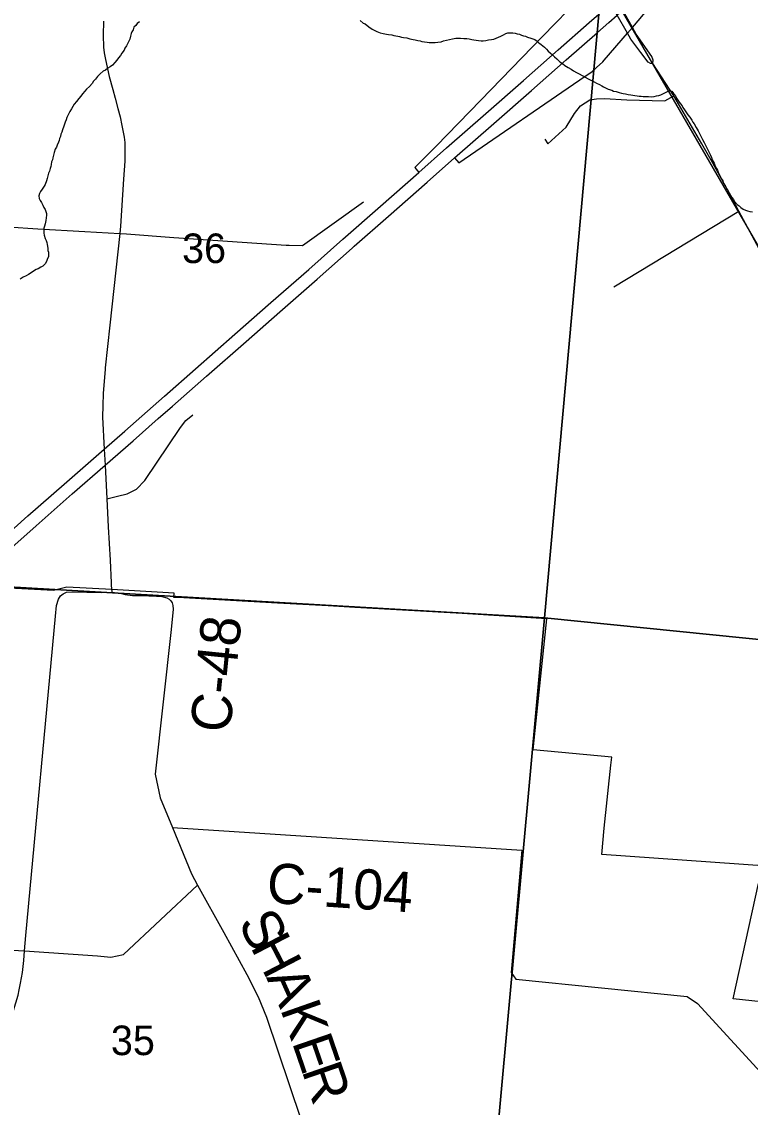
# Model space of a CAD drawing. Extents: x -7.3 to 34, y 0 to 22.
# Drawn here: x 5.697 to 6.729, y 15.258 to 16.795 of the extents above; entities that cross this region are included whole.
import ezdxf

# ---------------------------------------------------------------- set-up
doc = ezdxf.new("R2010")
doc.units = 0
for name, color, linetype in [('GM_X_City_Street', 7, 'Continuous'), ('GM_X_Corporation', 7, 'Continuous'), ('GM_X_County_Road', 7, 'Continuous'), ('GM_X_County_Road_Text', 7, 'Continuous'), ('GM_X_Interchange_Ramps', 7, 'Continuous'), ('GM_X_Interstate_Route', 7, 'Continuous'), ('GM_X_Minor_River', 7, 'Continuous'), ('GM_X_Rail_Line', 7, 'Continuous'), ('GM_X_Section_Text', 7, 'Continuous'), ('GM_X_State_Route', 7, 'Continuous'), ('GM_X_Township_Road', 7, 'Continuous')]:
    doc.layers.add(name, color=color, linetype=linetype)

msp = doc.modelspace()

# ---------------------------------------------------------------- linework, layer by layer
at = {"layer": 'GM_X_City_Street'}
for p, q in [((6.0944, 16.4782), (6.1808, 16.5402)), ((6.5355, 16.4199), (6.7126, 16.5267))]:
    msp.add_line(p, q, dxfattribs=at)
for points in [[(6.438, 16.629), (6.4421, 16.6224), (6.4681, 16.6457), (6.4797, 16.6651), (6.4884, 16.676), (6.5014, 16.6844), (6.5111, 16.6862), (6.5222, 16.6866), (6.5538, 16.6848), (6.6077, 16.6833), (6.6205, 16.6905)], [(5.817, 16.1194), (5.8323, 16.1231), (5.8461, 16.1267), (5.8591, 16.1332), (5.8709, 16.1456), (5.9218, 16.2206), (5.9292, 16.2303), (5.939, 16.2382)]]:
    msp.add_lwpolyline(points, dxfattribs=at)
at = {"layer": 'GM_X_Corporation'}
for points in [[(6.5281, 16.9583), (6.4371, 15.9508), (5.3843, 16.0117), (5.4793, 17.0267)], [(7.5781, 16.8709), (7.4799, 15.8457), (6.4371, 15.9508), (6.5281, 16.9583)], [(5.3843, 16.0117), (6.4371, 15.9508), (6.3438, 14.9266), (5.2968, 14.9953)], [(6.4371, 15.9508), (7.4799, 15.8457), (7.3939, 14.8252), (6.3438, 14.9266)]]:
    msp.add_lwpolyline(points, close=True, dxfattribs=at)
for points in [[(6.7526, 15.5989), (6.5186, 15.6157), (6.522, 15.653), (6.5314, 15.7421), (6.5326, 15.7533), (6.4213, 15.7638), (6.4256, 15.8049), (6.4405, 15.9496), (6.3205, 15.9572), (6.1686, 15.9656), (6.1308, 15.9677), (6.059, 15.9717), (5.918, 15.9795), (5.9123, 15.9798), (5.9126, 15.9859), (5.8241, 15.9908), (5.7607, 15.9943), (5.7415, 15.9894), (5.6604, 15.9938)], [(6.7577, 15.4057), (6.7044, 15.4109), (6.7404, 15.5743)]]:
    msp.add_lwpolyline(points, dxfattribs=at)
at = {"layer": 'GM_X_County_Road'}
for points in [[(5.8123, 16.7959), (5.8119, 16.776), (5.8127, 16.7593), (5.8135, 16.7514), (5.8152, 16.7418), (5.8205, 16.7178), (5.8255, 16.6994), (5.8289, 16.6868), (5.8327, 16.6725), (5.836, 16.6604), (5.8386, 16.6483), (5.8405, 16.6388), (5.8416, 16.6318), (5.8425, 16.624), (5.8429, 16.6151), (5.8428, 16.6085), (5.8425, 16.5979), (5.8408, 16.5721), (5.8366, 16.5057), (5.8357, 16.4953), (5.8213, 16.3654), (5.8147, 16.3051), (5.8146, 16.3031)], [(5.8146, 16.3031), (5.812, 16.2688), (5.8115, 16.2516)], [(5.8115, 16.2516), (5.8111, 16.2353), (5.8135, 16.1898), (5.8147, 16.1671), (5.817, 16.1194), (5.8189, 16.0796), (5.8217, 16.0324), (5.8233, 16.0003), (5.8235, 15.9973)], [(5.8235, 15.9973), (5.8242, 15.987), (5.8359, 15.9856), (5.843, 15.9839), (5.8535, 15.9827), (5.8654, 15.9823), (5.8876, 15.9815), (5.8951, 15.9811), (5.9021, 15.9793), (5.9054, 15.9775), (5.908, 15.9751), (5.9097, 15.972), (5.9108, 15.9682), (5.9111, 15.9632), (5.9082, 15.9345), (5.8859, 15.7294), (5.8926, 15.6958), (5.9101, 15.654)], [(5.7005, 15.479), (5.7025, 15.501), (5.7446, 15.953), (5.746, 15.9682), (5.7485, 15.9775), (5.7517, 15.9821), (5.7551, 15.9849), (5.76, 15.987), (5.7672, 15.9879), (5.8101, 15.9867), (5.8242, 15.987)], [(5.9101, 15.654), (5.9371, 15.588), (5.9458, 15.5723)], [(5.9101, 15.654), (6.405, 15.6216), (6.39, 15.4485), (6.3969, 15.4388), (6.6396, 15.4146), (6.6541, 15.4047), (7.0106, 15.016), (7.0281, 15.003), (7.4002, 14.9537)], [(5.2631, 15.5069), (5.2998, 15.5038), (5.3423, 15.5008), (5.4051, 15.4965), (5.4762, 15.4913), (5.5226, 15.4888), (5.5852, 15.4858), (5.6578, 15.4813), (5.7005, 15.479), (5.8041, 15.4719), (5.823, 15.4702), (5.841, 15.4739), (5.9458, 15.5723)], [(5.9458, 15.5723), (5.983, 15.5051), (6.0156, 15.4458), (6.0314, 15.4138), (6.0435, 15.385), (6.1085, 15.1916), (6.1202, 15.1639), (6.1228, 15.1187), (6.1105, 14.9604), (6.1114, 14.9539), (6.1126, 14.9497), (6.1149, 14.9453), (6.1189, 14.9421), (6.124, 14.9396), (6.1297, 14.9384), (6.135, 14.9379), (6.1434, 14.9376), (6.3268, 14.9272), (6.3325, 14.9245), (6.3377, 14.9197), (6.3407, 14.9122), (6.3395, 14.9005), (6.265, 14.1)], [(5.219, 14.1), (5.2383, 14.3304), (5.2709, 14.7021), (5.2768, 14.7107), (5.3257, 14.7637), (5.4619, 14.9128), (5.492, 14.945), (5.517, 14.9838), (5.5831, 15.0835), (5.6007, 15.1153), (5.611, 15.1424), (5.6526, 15.2909), (5.6914, 15.4165), (5.6931, 15.4241), (5.695, 15.4332), (5.6976, 15.4484), (5.6994, 15.4652), (5.7005, 15.479)]]:
    msp.add_lwpolyline(points, dxfattribs=at)
at = {"layer": 'GM_X_Interchange_Ramps'}
for p, q in [((6.522, 16.7408), (6.5551, 16.7789)), ((6.5551, 16.7789), (6.5621, 16.7871))]:
    msp.add_line(p, q, dxfattribs=at)
for points in [[(6.5621, 16.7871), (6.5649, 16.7906), (6.5956, 16.8273), (6.6184, 16.8544), (6.6365, 16.8741), (6.6473, 16.8856), (6.6419, 16.8935)], [(6.5195, 16.8633), (6.5117, 16.8544), (6.4889, 16.8307), (6.4346, 16.7745), (6.3469, 16.6841), (6.284, 16.6192), (6.2535, 16.589), (6.2594, 16.5819)], [(6.3099, 16.6023), (6.316, 16.5953), (6.495, 16.7181), (6.5042, 16.7241), (6.5112, 16.7302), (6.52, 16.7385), (6.522, 16.7408)]]:
    msp.add_lwpolyline(points, dxfattribs=at)
at = {"layer": 'GM_X_Interstate_Route'}
for points in [[(6.5285, 16.7942), (6.5403, 16.8047), (6.5484, 16.8118), (6.5982, 16.8552), (6.6419, 16.8935), (6.7013, 16.9459), (6.8071, 17.039), (6.8463, 17.0736), (6.8936, 17.1174), (6.9089, 17.1322)], [(6.2594, 16.5819), (6.2984, 16.6165), (6.354, 16.6652), (6.4075, 16.712), (6.4567, 16.7553), (6.5008, 16.794), (6.5313, 16.8207)], [(6.1676, 16.4771), (6.2165, 16.5199), (6.271, 16.5681), (6.3099, 16.6023), (6.3654, 16.6511), (6.419, 16.6979), (6.4682, 16.7411), (6.5123, 16.7799), (6.5285, 16.7942)], [(5.6667, 16.0604), (5.7054, 16.0951), (5.7567, 16.14), (5.8135, 16.1898), (5.8429, 16.2155), (5.8988, 16.2647), (5.9427, 16.3036), (5.9985, 16.3528), (6.0497, 16.3976), (6.1034, 16.4445), (6.1517, 16.4873), (6.205, 16.534), (6.2594, 16.5819)], [(5.89, 16.233), (5.9104, 16.2509), (5.9586, 16.2933), (6.0147, 16.3424), (6.0621, 16.3841), (6.115, 16.4307), (6.1646, 16.4744), (6.1676, 16.4771)], [(5.6362, 16.0066), (5.6783, 16.0466), (5.7171, 16.0813), (5.7683, 16.1263), (5.8147, 16.1671), (5.8545, 16.2017), (5.89, 16.233)]]:
    msp.add_lwpolyline(points, dxfattribs=at)
at = {"layer": 'GM_X_Minor_River'}
for points in [[(5.8634, 16.7953), (5.8603, 16.7927), (5.8583, 16.7901), (5.8556, 16.7875), (5.8544, 16.7837), (5.8524, 16.7811), (5.8516, 16.7785), (5.8508, 16.7747), (5.8496, 16.7705), (5.8483, 16.7675), (5.8467, 16.7638), (5.8452, 16.7611), (5.8428, 16.7578), (5.8416, 16.7548), (5.8385, 16.7506), (5.8365, 16.7473), (5.8338, 16.7439), (5.8315, 16.7409), (5.8284, 16.7376), (5.8252, 16.7338), (5.8221, 16.7312), (5.8187, 16.7294), (5.8152, 16.7268), (5.8121, 16.725), (5.8079, 16.7213), (5.804, 16.7176), (5.8009, 16.7138), (5.7982, 16.7109), (5.7966, 16.7079), (5.7927, 16.7034), (5.7885, 16.6997), (5.7861, 16.6971), (5.7826, 16.6933), (5.7803, 16.69), (5.7776, 16.6866), (5.774, 16.6821), (5.7709, 16.6784), (5.769, 16.6754), (5.767, 16.672), (5.765, 16.6683), (5.763, 16.6641), (5.7607, 16.6596), (5.7594, 16.6562), (5.7582, 16.6528), (5.7562, 16.6475), (5.7546, 16.6419), (5.7534, 16.6389), (5.7522, 16.6359), (5.7514, 16.6328), (5.7501, 16.6298), (5.7497, 16.6272), (5.7485, 16.6245), (5.7469, 16.6204), (5.7457, 16.6178), (5.7441, 16.6148), (5.7425, 16.6102), (5.7417, 16.6064), (5.7408, 16.6023), (5.74, 16.5996), (5.7388, 16.5966), (5.7384, 16.5932), (5.7379, 16.5902), (5.7371, 16.5872), (5.7359, 16.5834), (5.7347, 16.5808), (5.7338, 16.577), (5.7326, 16.5732), (5.7318, 16.5698), (5.7298, 16.5649), (5.7282, 16.5623), (5.7255, 16.5582), (5.7231, 16.5548), (5.7219, 16.5518), (5.7207, 16.5484), (5.7214, 16.5449), (5.7228, 16.5419), (5.7247, 16.5392), (5.7265, 16.5353), (5.7279, 16.5323), (5.7298, 16.5292), (5.7308, 16.5265), (5.7315, 16.5238), (5.7319, 16.5212), (5.7314, 16.5174), (5.7306, 16.5136), (5.7297, 16.509), (5.7289, 16.5056), (5.728, 16.5026), (5.728, 16.4996), (5.7279, 16.4958), (5.7286, 16.4927), (5.73, 16.4881), (5.7311, 16.4855)], [(6.1763, 16.7969), (6.1804, 16.7934), (6.1831, 16.7922), (6.1883, 16.7879), (6.1931, 16.7847), (6.1958, 16.7831), (6.1999, 16.7812), (6.2044, 16.7795), (6.2085, 16.7787), (6.2135, 16.7778), (6.2161, 16.7774), (6.221, 16.7765), (6.2237, 16.7757), (6.2267, 16.7753), (6.2293, 16.7748), (6.232, 16.7744), (6.2346, 16.7736), (6.2376, 16.7731), (6.2422, 16.7723), (6.2467, 16.771), (6.2512, 16.7702), (6.2539, 16.7697), (6.2576, 16.7685), (6.261, 16.768), (6.2637, 16.7672), (6.2671, 16.7668), (6.2712, 16.7663), (6.2739, 16.7659), (6.2788, 16.7658), (6.2822, 16.7657), (6.286, 16.7664), (6.291, 16.767), (6.2944, 16.7681), (6.2986, 16.7691), (6.3028, 16.7702), (6.307, 16.7712), (6.3116, 16.7719), (6.3157, 16.7722), (6.3184, 16.7721), (6.3229, 16.7716), (6.3271, 16.7715), (6.3305, 16.7711), (6.3343, 16.7702), (6.3373, 16.7694), (6.3403, 16.769), (6.3437, 16.7685), (6.3475, 16.7681), (6.3502, 16.7684), (6.354, 16.7687), (6.3578, 16.7694), (6.362, 16.77), (6.3654, 16.7707), (6.3688, 16.7718), (6.3719, 16.7732), (6.3754, 16.775), (6.3792, 16.7769), (6.3826, 16.7787), (6.3853, 16.7794), (6.388, 16.7793), (6.3925, 16.7796), (6.3956, 16.7792), (6.3986, 16.7783), (6.402, 16.7775), (6.4046, 16.7763), (6.4076, 16.7755), (6.4102, 16.7747), (6.4133, 16.7735), (6.4178, 16.7718), (6.4208, 16.771), (6.4234, 16.7702), (6.4268, 16.7678), (6.4294, 16.7655), (6.4327, 16.7628), (6.4372, 16.7593), (6.4402, 16.7562), (6.4424, 16.7534), (6.4454, 16.7511), (6.4487, 16.7484), (6.4513, 16.7457), (6.4547, 16.7425), (6.4592, 16.7386), (6.4629, 16.7359), (6.4662, 16.7332), (6.4707, 16.7304), (6.4749, 16.728), (6.4786, 16.7257), (6.4827, 16.7233), (6.4865, 16.7213), (6.4906, 16.719), (6.4951, 16.7166), (6.4992, 16.7146), (6.5022, 16.713), (6.5048, 16.7114), (6.5075, 16.7102), (6.5108, 16.7083), (6.515, 16.7063), (6.5183, 16.7043), (6.521, 16.7031)], [(6.521, 16.7031), (6.5247, 16.7011), (6.5273, 16.6999), (6.5326, 16.6983), (6.5352, 16.6971), (6.539, 16.6962), (6.5432, 16.695), (6.5462, 16.6942), (6.5488, 16.6937), (6.5522, 16.6929), (6.556, 16.6924), (6.5594, 16.6916), (6.5624, 16.6912), (6.5651, 16.6907), (6.5685, 16.6903), (6.5715, 16.6898), (6.5742, 16.6898), (6.5772, 16.6893), (6.581, 16.6892), (6.5848, 16.6892), (6.5889, 16.6891), (6.5927, 16.6894), (6.5958, 16.6901), (6.5992, 16.6907), (6.6023, 16.6918), (6.605, 16.6933), (6.608, 16.6944), (6.6107, 16.6958), (6.6141, 16.6973), (6.6175, 16.6968), (6.6201, 16.6937), (6.6224, 16.691), (6.6242, 16.6868), (6.6271, 16.6829), (6.6297, 16.6794), (6.6323, 16.6763), (6.6334, 16.6737), (6.6356, 16.6706), (6.6374, 16.6675), (6.6403, 16.6636), (6.6433, 16.6601), (6.6459, 16.6559), (6.6473, 16.6532), (6.6492, 16.6505), (6.6521, 16.6455), (6.655, 16.6405), (6.6565, 16.6378), (6.659, 16.6332), (6.6612, 16.6286), (6.6634, 16.6244), (6.6656, 16.6205), (6.6667, 16.6178), (6.6685, 16.6136), (6.6707, 16.6098), (6.6725, 16.6063), (6.6739, 16.6029), (6.675, 16.5998), (6.6775, 16.5948), (6.6786, 16.5921), (6.6812, 16.5875), (6.6822, 16.5848), (6.6833, 16.5821), (6.6855, 16.5775), (6.6877, 16.5733), (6.6899, 16.5698), (6.6909, 16.566), (6.6932, 16.5633), (6.6953, 16.5591), (6.6972, 16.556), (6.699, 16.5529), (6.7008, 16.5498), (6.7027, 16.5464), (6.7049, 16.5433), (6.7067, 16.5406), (6.7104, 16.5363), (6.713, 16.5344), (6.7156, 16.532), (6.719, 16.5297), (6.722, 16.5285), (6.725, 16.5273), (6.7284, 16.5264), (6.7322, 16.526)], [(5.7311, 16.4855), (5.7321, 16.4824), (5.7325, 16.4797), (5.7332, 16.4771), (5.7335, 16.474), (5.7338, 16.4713), (5.7345, 16.4687), (5.7344, 16.466), (5.7344, 16.4626), (5.7328, 16.4584), (5.7316, 16.4554), (5.7296, 16.4521), (5.7265, 16.4491), (5.7238, 16.4476), (5.72, 16.4454), (5.7173, 16.4443), (5.7134, 16.4421), (5.71, 16.4396), (5.7061, 16.4374), (5.7027, 16.4355), (5.6988, 16.4333), (5.6946, 16.4308)]]:
    msp.add_lwpolyline(points, dxfattribs=at)
at = {"layer": 'GM_X_Rail_Line'}
msp.add_lwpolyline([(8.1171, 14.1), (7.77, 14.7008), (7.4272, 15.293), (6.5394, 16.8246), (6.3886, 17.0851), (6.2996, 17.2555), (6.2775, 17.3138), (6.2567, 17.3864), (6.213, 17.5514), (6.1948, 17.6035), (6.1703, 17.6358), (6.1218, 17.6697), (5.9568, 17.7678)], dxfattribs=at)
at = {"layer": 'GM_X_State_Route'}
for points in [[(6.5551, 16.7789), (6.5403, 16.8047), (6.5313, 16.8207), (6.5117, 16.8544), (6.4933, 16.8962), (6.4928, 16.8988), (6.4942, 16.9015)], [(6.5621, 16.7871), (6.5484, 16.8118), (6.5394, 16.8278), (6.5195, 16.8633), (6.5148, 16.8715)], [(6.5908, 16.736), (6.5875, 16.7361), (6.5844, 16.7381), (6.5738, 16.7518), (6.5598, 16.7706), (6.5551, 16.7789)], [(6.5908, 16.736), (6.5911, 16.7406), (6.5893, 16.746), (6.5674, 16.7778), (6.5621, 16.7871)], [(6.8348, 16.3126), (6.7973, 16.3768), (6.7511, 16.4561), (6.7126, 16.5267), (6.6993, 16.5519), (6.6751, 16.5958), (6.6603, 16.6222), (6.6205, 16.6905), (6.5908, 16.736)]]:
    msp.add_lwpolyline(points, dxfattribs=at)
at = {"layer": 'GM_X_Township_Road'}
msp.add_line((6.0753, 16.4786), (6.0944, 16.4782), dxfattribs=at)
for points in [[(5.2451, 16.542), (5.3625, 16.5287), (5.487, 16.518), (5.6773, 16.5048), (5.7195, 16.502), (5.7858, 16.4982), (5.8357, 16.4953), (5.8452, 16.4946)], [(5.8452, 16.4946), (5.912, 16.4898), (6.0715, 16.4786), (6.0753, 16.4786)]]:
    msp.add_lwpolyline(points, dxfattribs=at)

# ---------------------------------------------------------------- texts
at = {"layer": 'GM_X_County_Road_Text'}
for s, height, rotation, p in [('C-48', 0.05682, 84.1533, (5.9916, 15.7867)), ('C-104', 0.05682, 356.1494, (6.0426, 15.5474)), ('S', 0.0568, 297.5574, (6.0022, 15.519)), ('H', 0.0568, 297.4187, (6.0199, 15.4851)), ('A', 0.0568, 294.1386, (6.0426, 15.4415)), ('K', 0.0568, 289.3485, (6.0625, 15.397)), ('E', 0.0568, 288.9784, (6.0791, 15.3499)), ('R', 0.0568, 288.9694, (6.0929, 15.3097))]:
    msp.add_text(s, height=height, rotation=rotation, dxfattribs=at).set_placement(p)
at = {"layer": 'GM_X_Section_Text'}
for s, p in [('36', (5.9238, 16.4534)), ('35', (5.823, 15.3314))]:
    msp.add_text(s, height=0.04186, rotation=0, dxfattribs=at).set_placement(p)

doc.saveas('drawing.dxf')
